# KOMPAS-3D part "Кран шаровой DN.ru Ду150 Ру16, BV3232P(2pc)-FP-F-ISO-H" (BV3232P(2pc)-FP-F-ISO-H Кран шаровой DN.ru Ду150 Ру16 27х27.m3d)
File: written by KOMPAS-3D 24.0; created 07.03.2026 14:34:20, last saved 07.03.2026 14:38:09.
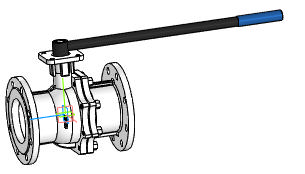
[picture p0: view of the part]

Document properties: Автор: R2D2; Полное имя файла: BV3232P(2pc)-FP-F-ISO-H Кран шаровой DN.ru Ду150 Ру16 27х27.cdw

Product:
- Part/product: Кран шаровой DN.ru Ду150 Ру16  | designation BV3232P(2pc)-FP-F-ISO-H
    Масса: 41
    Раздел спецификации: Прочие изделия
    Форматы листов документа: A2
    Примечание: D160-22161

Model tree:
1. Операция без истории:1

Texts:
  BV3232P(2pc)-FP-F-ISO-H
